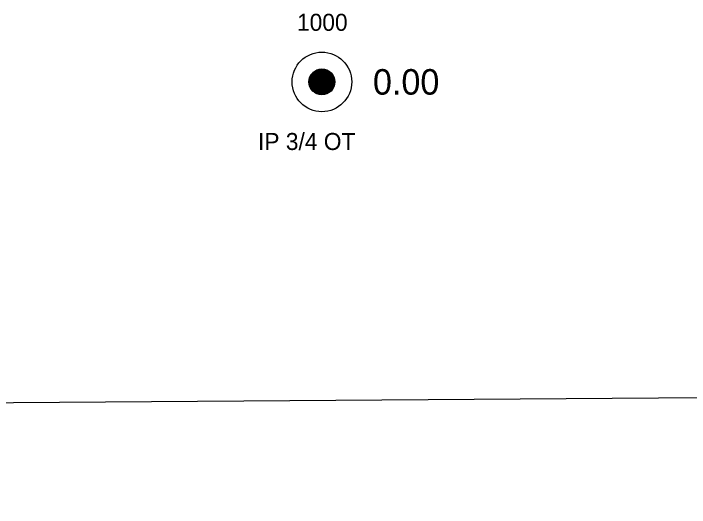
# Model space of a CAD drawing. Extents: x 1529475 to 1532053, y 876698 to 877911.
# Drawn here: x 1531089.27 to 1531129.01, y 877286.3 to 877315.31 of the extents above; entities that cross this region are included whole.
import ezdxf

# ---------------------------------------------------------------- set-up
doc = ezdxf.new("R2010")
doc.units = 0
for name, color, linetype in [('RD_EX_DV_Prop_txCode', 7, 'Continuous'), ('RD_EX_DV_PropPin', 7, 'Continuous'), ('RD_EX_Road', 7, 'Continuous'), ('RD_EX_TX_DV_Prop_ELEV', 7, 'Continuous'), ('RD_SMD_Locator', 7, 'Continuous')]:
    doc.layers.add(name, color=color, linetype=linetype)

msp = doc.modelspace()

# ---------------------------------------------------------------- linework, layer by layer
at = {"layer": 'RD_EX_DV_PropPin'}
for p, q in [((1531106.913, 877310.717), (1531106.913, 877311.881)), ((1531106.948, 877310.689), (1531106.948, 877311.909)), ((1531106.983, 877310.664), (1531106.983, 877311.934)), ((1531107.018, 877310.643), (1531107.018, 877311.955)), ((1531107.053, 877310.623), (1531107.053, 877311.975)), ((1531107.088, 877310.606), (1531107.088, 877311.992)), ((1531107.123, 877310.591), (1531107.123, 877312.007)), ((1531107.158, 877310.579), (1531107.158, 877312.019)), ((1531107.193, 877310.568), (1531107.193, 877312.03)), ((1531107.228, 877310.558), (1531107.228, 877312.04)), ((1531107.263, 877310.551), (1531107.263, 877312.047)), ((1531107.298, 877310.545), (1531107.298, 877312.053)), ((1531107.333, 877310.541), (1531107.333, 877312.057)), ((1531107.368, 877310.539), (1531107.368, 877312.059)), ((1531107.403, 877310.538), (1531107.403, 877312.06)), ((1531107.438, 877310.539), (1531107.438, 877312.059)), ((1531107.473, 877310.541), (1531107.473, 877312.057)), ((1531107.508, 877310.545), (1531107.508, 877312.053)), ((1531107.543, 877310.551), (1531107.543, 877312.047)), ((1531107.578, 877310.558), (1531107.578, 877312.04)), ((1531107.613, 877310.568), (1531107.613, 877312.03)), ((1531107.648, 877310.579), (1531107.648, 877312.019)), ((1531107.683, 877310.591), (1531107.683, 877312.007)), ((1531107.718, 877310.606), (1531107.718, 877311.992)), ((1531107.753, 877310.623), (1531107.753, 877311.975)), ((1531107.788, 877310.643), (1531107.788, 877311.955)), ((1531107.823, 877310.664), (1531107.823, 877311.934)), ((1531107.858, 877310.689), (1531107.858, 877311.909)), ((1531107.893, 877310.717), (1531107.893, 877311.881)), ((1531106.668, 877311.103), (1531106.668, 877311.495)), ((1531106.703, 877311.001), (1531106.703, 877311.597)), ((1531106.738, 877310.929), (1531106.738, 877311.669)), ((1531106.773, 877310.872), (1531106.773, 877311.726)), ((1531106.808, 877310.825), (1531106.808, 877311.773)), ((1531106.843, 877310.784), (1531106.843, 877311.814)), ((1531106.878, 877310.748), (1531106.878, 877311.85)), ((1531107.928, 877310.748), (1531107.928, 877311.85)), ((1531107.963, 877310.784), (1531107.963, 877311.814)), ((1531107.998, 877310.825), (1531107.998, 877311.773)), ((1531108.033, 877310.872), (1531108.033, 877311.726)), ((1531108.068, 877310.929), (1531108.068, 877311.669)), ((1531108.103, 877311.001), (1531108.103, 877311.597)), ((1531108.138, 877311.103), (1531108.138, 877311.495))]:
    msp.add_line(p, q, dxfattribs=at)
for radius in [1.75, 0.761]:
    msp.add_circle((1531107.403, 877311.299), radius, dxfattribs=at)
at = {"layer": 'RD_EX_Road'}
msp.add_lwpolyline([(1531606.641, 877133.837), (1531579.15, 877155.048), (1531564.866, 877165.268), (1531535.216, 877186.029), (1531511.532, 877200.27), (1531474.57, 877218.901), (1531430.451, 877239.347), (1531404.48, 877249.379), (1531382.323, 877256.431), (1531333.233, 877270.709), (1531303.666, 877277.444), (1531276.518, 877282.709), (1531237.324, 877287.202), (1531185.802, 877290.94), (1531132.609, 877292.767), (1531081.114, 877292.384), (1531038.69, 877288.667), (1530976.423, 877285.451), (1530941.057, 877284.256)], dxfattribs=at)
at = {"layer": 'RD_SMD_Locator'}
msp.add_circle((1531107.403, 877311.299), 0.15, dxfattribs=at)

# ---------------------------------------------------------------- texts
at = {"layer": 'RD_EX_DV_Prop_txCode'}
for s, p in [('1000', (1531105.938, 877314.299)), ('IP 3/4 OT', (1531103.647, 877307.299))]:
    msp.add_text(s, height=1, dxfattribs=at).set_placement(p)
at = {"layer": 'RD_EX_TX_DV_Prop_ELEV'}
msp.add_text('0.00', height=1.5, dxfattribs=at).set_placement((1531110.403, 877310.549))

doc.saveas('drawing.dxf')
